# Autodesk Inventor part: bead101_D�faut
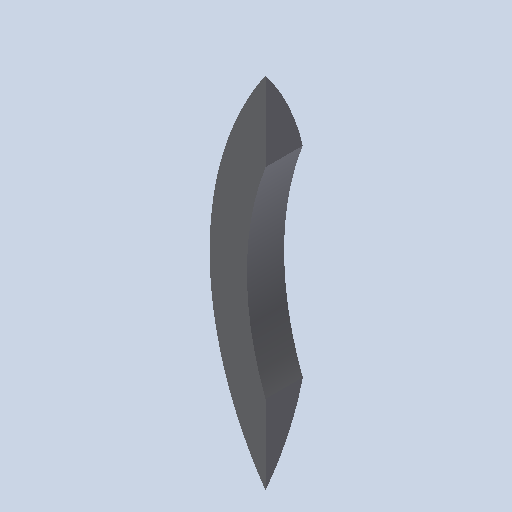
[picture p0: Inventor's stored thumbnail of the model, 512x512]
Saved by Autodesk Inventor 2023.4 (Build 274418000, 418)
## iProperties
Created: 2011-01
Part Number: bead101_D�faut
Document SubType Name: Modeling
Designer: eric
Density: 1 g/cm^3
Mass: 0.0356546 g
Surface Area: 1.11254 cm^2
Volume: 0.0356546 cm^3
Material: Générique
Appearance: Par défaut
Author: eric
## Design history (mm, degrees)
feature "Base1"
node "Corps solides"
node "Corps surfaciques"
node "Solide1"
